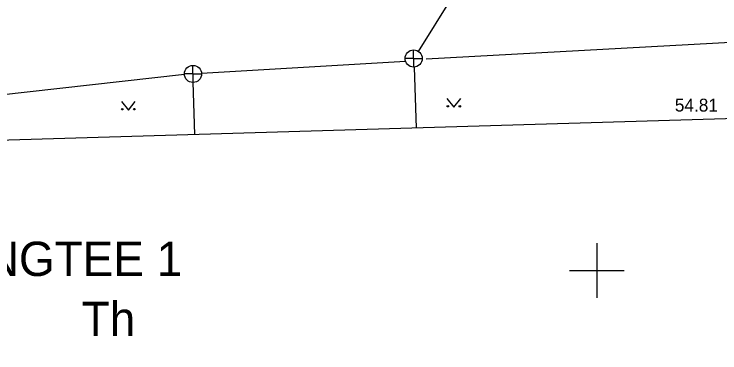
# Model space of a CAD drawing. Extents: x 9156 to 9809, y 2728 to 4000.
# Drawn here: x 9566.07 to 9607.17, y 3645.21 to 3664.94 of the extents above; entities that cross this region are included whole.
import ezdxf

# ---------------------------------------------------------------- set-up
doc = ezdxf.new("R2010")
doc.units = 0
for name, color, linetype in [('Level 5', 7, 'Continuous'), ('Level 54', 7, 'Continuous'), ('Level 58', 7, 'Continuous')]:
    doc.layers.add(name, color=color, linetype=linetype)

# ---------------------------------------------------------------- blocks, each defined once
blk = doc.blocks.new('KKOL')
at = {"layer": 'Level 58'}
for p, q in [((0, 1.59349), (0, -1.5935)), ((-1.5935, 0), (1.59349, 0))]:
    blk.add_line(p, q, dxfattribs=at)

msp = doc.modelspace()

# ---------------------------------------------------------------- linework, layer by layer
at = {"layer": 'Level 54'}
for p, q in [((9589.626, 3662.764), (9593.338, 3668.737)), ((9617.383, 3663.818), (9590.062, 3662.322)), ((9589.335, 3662.357), (9589.335, 3662.857)), ((9576.984, 3661.502), (9588.857, 3662.211)), ((9589.335, 3662.357), (9588.835, 3662.357)), ((9589.335, 3662.357), (9589.835, 3662.357)), ((9589.335, 3662.357), (9589.335, 3661.857)), ((9576.486, 3661.46), (9576.486, 3661.96)), ((9589.377, 3661.859), (9589.481, 3658.308)), ((9561.05, 3659.763), (9575.986, 3661.444)), ((9576.486, 3661.46), (9575.986, 3661.46)), ((9576.486, 3661.46), (9576.986, 3661.46)), ((9576.486, 3661.46), (9576.486, 3660.96)), ((9576.486, 3660.989), (9576.581, 3657.928)), ((9661.889, 3660.444), (9561.995, 3657.498)), ((9572.32, 3659.855), (9572.723, 3659.349)), ((9572.723, 3659.349), (9573.12, 3659.855)), ((9591.278, 3660.027), (9591.681, 3659.521)), ((9591.681, 3659.521), (9592.078, 3660.027))]:
    msp.add_line(p, q, dxfattribs=at)
for centre, radius in [((9589.335, 3662.357), 0.5), ((9576.486, 3661.46), 0.5), ((9572.37, 3659.405), 0.0428), ((9573.07, 3659.405), 0.0452), ((9591.328, 3659.577), 0.0428), ((9592.028, 3659.577), 0.0452)]:
    msp.add_circle(centre, radius, dxfattribs=at)
msp.add_spline([(9551.163, 3554.03), (9551.63, 3553.617), (9552.412, 3553.356), (9553.456, 3553.552), (9550.134, 3650.407)], degree=3, dxfattribs=at)

# ---------------------------------------------------------------- block references
msp.add_blockref('KKOL', (9600, 3650), dxfattribs=at)

# ---------------------------------------------------------------- texts
at = {"layer": 'Level 5'}
for s, p in [('RINGTEE 1', (9561.742, 3649.685)), ('Th', (9570.001, 3646.185))]:
    msp.add_text(s, height=2, dxfattribs=at).set_placement(p)
at = {"layer": 'Level 54'}
msp.add_text('54.81', height=0.75, dxfattribs=at).set_placement((9604.549, 3659.266))

doc.saveas('drawing.dxf')
